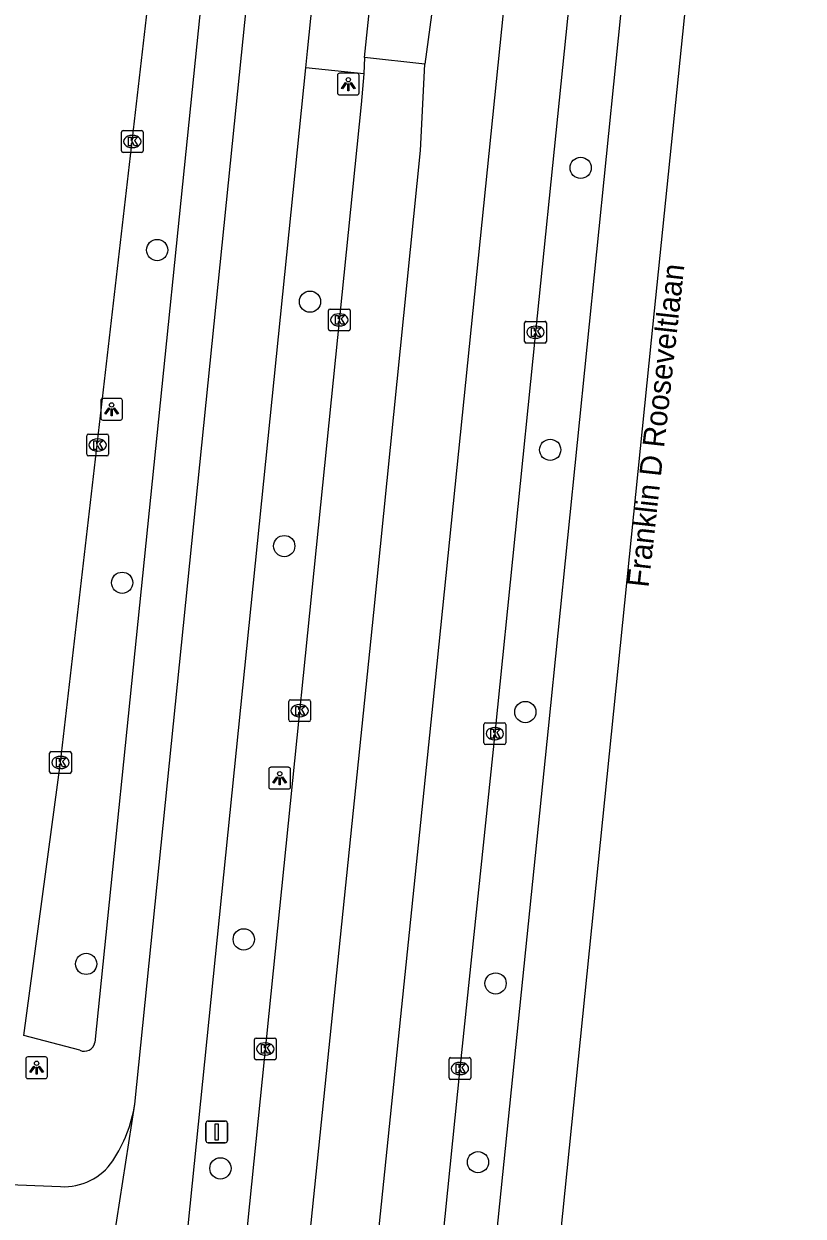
# Model space of a CAD drawing. Extents: x 160891 to 161384, y 386490 to 386907.
# Drawn here: x 161334.9 to 161370.7, y 386584.8 to 386639.6 of the extents above; entities that cross this region are included whole.
import ezdxf

# ---------------------------------------------------------------- set-up
doc = ezdxf.new("R2010")
doc.units = 0
for name, color, linetype in [('IMGEO_Boom', 7, 'Continuous'), ('IMGEO_Fietspad_gesloten', 7, 'Continuous'), ('IMGEO_Kolk', 7, 'Continuous'), ('IMGEO_Lichtpunt', 7, 'Continuous'), ('IMGEO_Openbare_ruimte_label', 7, 'Continuous'), ('IMGEO_Rijbaan_lokaal_gesloten', 7, 'Continuous'), ('IMGEO_Rijbaan_lokaal_open', 7, 'Continuous'), ('IMGEO_Verkeersbordpaal', 7, 'Continuous'), ('IMGEO_Voetpad_open', 7, 'Continuous')]:
    doc.layers.add(name, color=color, linetype=linetype)

msp = doc.modelspace()

# ---------------------------------------------------------------- linework, layer by layer
at = {"layer": 'IMGEO_Boom'}
for centre in [(161360.496, 386632.993), (161341.033, 386629.213), (161348.056, 386626.84), (161359.096, 386620.026), (161346.872, 386615.599), (161339.424, 386613.914), (161357.954, 386607.968), (161345.014, 386597.514), (161337.77, 386596.388), (161356.586, 386595.488), (161343.941, 386586.985), (161355.778, 386587.271)]:
    msp.add_circle(centre, 0.489, dxfattribs=at)
at = {"layer": 'IMGEO_Fietspad_gesloten'}
for points in [[(161340.003, 386589.938), (161344.586, 386635.023), (161348.773, 386676.071), (161350.75, 386695.389)], [(161336.452, 386525.646), (161336.548, 386526.649), (161337.443, 386534.03), (161338.136, 386542.124), (161339.032, 386551.069), (161341.141, 386571.584), (161342.161, 386581.483), (161347.861, 386637.589)], [(161338.485, 386580.159), (161340.003, 386589.938)], [(161314.741, 386587.177), (161314.693, 386587.03), (161314.685, 386587.006), (161336.596, 386586.148)]]:
    msp.add_lwpolyline(points, dxfattribs=at)
for centre, radius, start, end in [((161333.422, 386590.984), 6.663, 326.7857, 350.9683), ((161336.756, 386588.847), 2.704, 266.6, 325.9751)]:
    msp.add_arc(centre, radius, start, end, dxfattribs=at)
at = {"layer": 'IMGEO_Kolk'}
for p, q in [((161339.392, 386633.778), (161339.392, 386634.63)), ((161339.467, 386634.704), (161340.319, 386634.704)), ((161340.393, 386634.63), (161340.393, 386633.778)), ((161339.88, 386634.484), (161339.905, 386634.484)), ((161340.319, 386633.704), (161339.467, 386633.704)), ((161339.903, 386633.924), (161339.878, 386633.924)), ((161348.903, 386625.576), (161348.903, 386626.428)), ((161348.978, 386626.502), (161349.83, 386626.502)), ((161349.391, 386626.282), (161349.416, 386626.282)), ((161349.904, 386626.428), (161349.904, 386625.576)), ((161349.414, 386625.722), (161349.389, 386625.722)), ((161357.922, 386625.009), (161357.922, 386625.861)), ((161357.997, 386625.935), (161358.849, 386625.935)), ((161358.923, 386625.861), (161358.923, 386625.009)), ((161349.83, 386625.502), (161348.978, 386625.502)), ((161358.41, 386625.715), (161358.435, 386625.715)), ((161358.849, 386624.935), (161357.997, 386624.935)), ((161358.433, 386625.155), (161358.408, 386625.155)), ((161337.798, 386619.821), (161337.798, 386620.673)), ((161337.873, 386620.747), (161338.725, 386620.747)), ((161338.286, 386620.527), (161338.311, 386620.527)), ((161338.799, 386620.673), (161338.799, 386619.821)), ((161338.725, 386619.747), (161337.873, 386619.747)), ((161338.309, 386619.967), (161338.284, 386619.967)), ((161347.081, 386607.605), (161347.081, 386608.457)), ((161347.156, 386608.531), (161348.008, 386608.531)), ((161347.569, 386608.311), (161347.594, 386608.311)), ((161348.082, 386608.457), (161348.082, 386607.605)), ((161347.592, 386607.751), (161347.567, 386607.751)), ((161348.008, 386607.531), (161347.156, 386607.531)), ((161356.052, 386606.549), (161356.052, 386607.401)), ((161356.127, 386607.475), (161356.979, 386607.475)), ((161356.54, 386607.255), (161356.565, 386607.255)), ((161357.053, 386607.401), (161357.053, 386606.549)), ((161356.563, 386606.695), (161356.538, 386606.695)), ((161336.091, 386605.222), (161336.091, 386606.074)), ((161336.166, 386606.148), (161337.018, 386606.148)), ((161337.092, 386606.074), (161337.092, 386605.222)), ((161356.979, 386606.475), (161356.127, 386606.475)), ((161336.579, 386605.928), (161336.604, 386605.928)), ((161337.018, 386605.148), (161336.166, 386605.148)), ((161336.602, 386605.368), (161336.577, 386605.368)), ((161345.504, 386592.052), (161345.504, 386592.904)), ((161345.579, 386592.978), (161346.431, 386592.978)), ((161346.505, 386592.904), (161346.505, 386592.052)), ((161345.992, 386592.758), (161346.017, 386592.758)), ((161346.431, 386591.978), (161345.579, 386591.978)), ((161346.015, 386592.198), (161345.99, 386592.198)), ((161354.447, 386591.15), (161354.447, 386592.002)), ((161354.522, 386592.076), (161355.374, 386592.076)), ((161354.935, 386591.856), (161354.96, 386591.856)), ((161355.448, 386592.002), (161355.448, 386591.15)), ((161354.958, 386591.296), (161354.933, 386591.296)), ((161355.374, 386591.076), (161354.522, 386591.076))]:
    msp.add_line(p, q, dxfattribs=at)
for points in [[(161339.392, 386633.778), (161339.392, 386634.63)], [(161339.467, 386634.704), (161340.319, 386634.704)], [(161340.393, 386634.63), (161340.393, 386633.778)], [(161339.713, 386634.404), (161339.836, 386634.404), (161339.836, 386634.253), (161339.966, 386634.404), (161340.13, 386634.404), (161339.984, 386634.253), (161340.137, 386634.004), (161339.985, 386634.004), (161339.9, 386634.168), (161339.836, 386634.101), (161339.836, 386634.004), (161339.713, 386634.004), (161339.713, 386634.404)], [(161340.319, 386633.704), (161339.467, 386633.704)], [(161348.903, 386625.576), (161348.903, 386626.428)], [(161348.978, 386626.502), (161349.83, 386626.502)], [(161349.904, 386626.428), (161349.904, 386625.576)], [(161349.224, 386626.202), (161349.347, 386626.202), (161349.347, 386626.051), (161349.477, 386626.202), (161349.641, 386626.202), (161349.495, 386626.051), (161349.648, 386625.802), (161349.496, 386625.802), (161349.411, 386625.966), (161349.347, 386625.899), (161349.347, 386625.802), (161349.224, 386625.802), (161349.224, 386626.202)], [(161357.922, 386625.009), (161357.922, 386625.861)], [(161357.997, 386625.935), (161358.849, 386625.935)], [(161358.923, 386625.861), (161358.923, 386625.009)], [(161349.83, 386625.502), (161348.978, 386625.502)], [(161358.243, 386625.635), (161358.366, 386625.635), (161358.366, 386625.484), (161358.496, 386625.635), (161358.66, 386625.635), (161358.514, 386625.484), (161358.667, 386625.235), (161358.515, 386625.235), (161358.43, 386625.399), (161358.366, 386625.332), (161358.366, 386625.235), (161358.243, 386625.235), (161358.243, 386625.635)], [(161358.849, 386624.935), (161357.997, 386624.935)], [(161337.798, 386619.821), (161337.798, 386620.673)], [(161337.873, 386620.747), (161338.725, 386620.747)], [(161338.119, 386620.447), (161338.242, 386620.447), (161338.242, 386620.296), (161338.372, 386620.447), (161338.536, 386620.447), (161338.39, 386620.296), (161338.543, 386620.047), (161338.391, 386620.047), (161338.306, 386620.211), (161338.242, 386620.144), (161338.242, 386620.047), (161338.119, 386620.047), (161338.119, 386620.447)], [(161338.799, 386620.673), (161338.799, 386619.821)], [(161338.725, 386619.747), (161337.873, 386619.747)], [(161347.081, 386607.605), (161347.081, 386608.457)], [(161347.156, 386608.531), (161348.008, 386608.531)], [(161347.402, 386608.231), (161347.525, 386608.231), (161347.525, 386608.08), (161347.655, 386608.231), (161347.819, 386608.231), (161347.673, 386608.08), (161347.826, 386607.831), (161347.674, 386607.831), (161347.589, 386607.995), (161347.525, 386607.928), (161347.525, 386607.831), (161347.402, 386607.831), (161347.402, 386608.231)], [(161348.082, 386608.457), (161348.082, 386607.605)], [(161348.008, 386607.531), (161347.156, 386607.531)], [(161356.052, 386606.549), (161356.052, 386607.401)], [(161356.127, 386607.475), (161356.979, 386607.475)], [(161356.373, 386607.175), (161356.496, 386607.175), (161356.496, 386607.024), (161356.626, 386607.175), (161356.79, 386607.175), (161356.644, 386607.024), (161356.797, 386606.775), (161356.645, 386606.775), (161356.56, 386606.939), (161356.496, 386606.872), (161356.496, 386606.775), (161356.373, 386606.775), (161356.373, 386607.175)], [(161357.053, 386607.401), (161357.053, 386606.549)], [(161336.091, 386605.222), (161336.091, 386606.074)], [(161336.166, 386606.148), (161337.018, 386606.148)], [(161337.092, 386606.074), (161337.092, 386605.222)], [(161356.979, 386606.475), (161356.127, 386606.475)], [(161336.412, 386605.848), (161336.535, 386605.848), (161336.535, 386605.697), (161336.665, 386605.848), (161336.829, 386605.848), (161336.683, 386605.697), (161336.836, 386605.448), (161336.684, 386605.448), (161336.599, 386605.612), (161336.535, 386605.545), (161336.535, 386605.448), (161336.412, 386605.448), (161336.412, 386605.848)], [(161337.018, 386605.148), (161336.166, 386605.148)], [(161345.504, 386592.052), (161345.504, 386592.904)], [(161345.579, 386592.978), (161346.431, 386592.978)], [(161346.505, 386592.904), (161346.505, 386592.052)], [(161345.825, 386592.678), (161345.948, 386592.678), (161345.948, 386592.527), (161346.078, 386592.678), (161346.242, 386592.678), (161346.096, 386592.527), (161346.249, 386592.278), (161346.097, 386592.278), (161346.012, 386592.442), (161345.948, 386592.375), (161345.948, 386592.278), (161345.825, 386592.278), (161345.825, 386592.678)], [(161346.431, 386591.978), (161345.579, 386591.978)], [(161354.447, 386591.15), (161354.447, 386592.002)], [(161354.522, 386592.076), (161355.374, 386592.076)], [(161354.768, 386591.776), (161354.891, 386591.776), (161354.891, 386591.625), (161355.021, 386591.776), (161355.185, 386591.776), (161355.039, 386591.625), (161355.192, 386591.376), (161355.04, 386591.376), (161354.955, 386591.54), (161354.891, 386591.473), (161354.891, 386591.376), (161354.768, 386591.376), (161354.768, 386591.776)], [(161355.448, 386592.002), (161355.448, 386591.15)], [(161355.374, 386591.076), (161354.522, 386591.076)]]:
    msp.add_lwpolyline(points, dxfattribs=at)
for centre, start, end in [((161339.469, 386634.628), 91.552, 178.448), ((161339.469, 386634.628), 91.552, 178.448), ((161340.317, 386634.628), 1.552, 88.448), ((161340.317, 386634.628), 1.552, 88.448), ((161339.469, 386633.78), 181.552, 268.448), ((161339.469, 386633.78), 181.552, 268.448), ((161340.317, 386633.78), 271.552, 358.448), ((161340.317, 386633.78), 271.552, 358.448), ((161348.98, 386626.426), 91.552, 178.448), ((161348.98, 386626.426), 91.552, 178.448), ((161349.828, 386626.426), 1.552, 88.448), ((161349.828, 386626.426), 1.552, 88.448), ((161357.999, 386625.859), 91.552, 178.448), ((161357.999, 386625.859), 91.552, 178.448), ((161358.847, 386625.859), 1.552, 88.448), ((161358.847, 386625.859), 1.552, 88.448), ((161348.98, 386625.578), 181.552, 268.448), ((161348.98, 386625.578), 181.552, 268.448), ((161349.828, 386625.578), 271.552, 358.448), ((161349.828, 386625.578), 271.552, 358.448), ((161357.999, 386625.011), 181.552, 268.448), ((161357.999, 386625.011), 181.552, 268.448), ((161358.847, 386625.011), 271.552, 358.448), ((161358.847, 386625.011), 271.552, 358.448), ((161337.875, 386620.671), 91.552, 178.448), ((161337.875, 386620.671), 91.552, 178.448), ((161338.723, 386620.671), 1.552, 88.448), ((161338.723, 386620.671), 1.552, 88.448), ((161337.875, 386619.823), 181.552, 268.448), ((161337.875, 386619.823), 181.552, 268.448), ((161338.723, 386619.823), 271.552, 358.448), ((161338.723, 386619.823), 271.552, 358.448), ((161347.158, 386608.455), 91.552, 178.448), ((161347.158, 386608.455), 91.552, 178.448), ((161348.006, 386608.455), 1.552, 88.448), ((161348.006, 386608.455), 1.552, 88.448), ((161347.158, 386607.607), 181.552, 268.448), ((161347.158, 386607.607), 181.552, 268.448), ((161348.006, 386607.607), 271.552, 358.448), ((161348.006, 386607.607), 271.552, 358.448), ((161356.129, 386607.399), 91.552, 178.448), ((161356.129, 386607.399), 91.552, 178.448), ((161356.977, 386607.399), 1.552, 88.448), ((161356.977, 386607.399), 1.552, 88.448), ((161356.129, 386606.551), 181.552, 268.448), ((161356.129, 386606.551), 181.552, 268.448), ((161356.977, 386606.551), 271.552, 358.448), ((161356.977, 386606.551), 271.552, 358.448), ((161336.168, 386606.072), 91.552, 178.448), ((161336.168, 386606.072), 91.552, 178.448), ((161337.016, 386606.072), 1.552, 88.448), ((161337.016, 386606.072), 1.552, 88.448), ((161336.168, 386605.224), 181.552, 268.448), ((161336.168, 386605.224), 181.552, 268.448), ((161337.016, 386605.224), 271.552, 358.448), ((161337.016, 386605.224), 271.552, 358.448), ((161345.581, 386592.902), 91.552, 178.448), ((161345.581, 386592.902), 91.552, 178.448), ((161346.429, 386592.902), 1.552, 88.448), ((161346.429, 386592.902), 1.552, 88.448), ((161345.581, 386592.054), 181.552, 268.448), ((161345.581, 386592.054), 181.552, 268.448), ((161346.429, 386592.054), 271.552, 358.448), ((161346.429, 386592.054), 271.552, 358.448), ((161354.524, 386592), 91.552, 178.448), ((161354.524, 386592), 91.552, 178.448), ((161355.372, 386592), 1.552, 88.448), ((161355.372, 386592), 1.552, 88.448), ((161354.524, 386591.152), 181.552, 268.448), ((161354.524, 386591.152), 181.552, 268.448), ((161355.372, 386591.152), 271.552, 358.448), ((161355.372, 386591.152), 271.552, 358.448)]:
    msp.add_arc(centre, 0.0765, start, end, dxfattribs=at)
for centre, major_axis, ratio, start_param, end_param in [((161339.879, 386634.204), (-0.387, 0.002), 0.722429, 4.712389, 7.853982), ((161339.904, 386634.204), (-0.39, 0.002), 0.717154, 1.570796, 4.712389), ((161349.39, 386626.002), (-0.387, 0.002), 0.722429, 4.712389, 7.853982), ((161349.415, 386626.002), (-0.39, 0.002), 0.717154, 1.570796, 4.712389), ((161358.409, 386625.435), (-0.387, 0.002), 0.722429, 4.712389, 7.853982), ((161358.434, 386625.435), (-0.39, 0.002), 0.717154, 1.570796, 4.712389), ((161338.285, 386620.247), (-0.387, 0.002), 0.722429, 4.712389, 7.853982), ((161338.31, 386620.247), (-0.39, 0.002), 0.717154, 1.570796, 4.712389), ((161347.568, 386608.031), (-0.387, 0.002), 0.722429, 4.712389, 7.853982), ((161347.593, 386608.031), (-0.39, 0.002), 0.717154, 1.570796, 4.712389), ((161356.539, 386606.975), (-0.387, 0.002), 0.722429, 4.712389, 7.853982), ((161356.564, 386606.975), (-0.39, 0.002), 0.717154, 1.570796, 4.712389), ((161336.578, 386605.648), (-0.387, 0.002), 0.722429, 4.712389, 7.853982), ((161336.603, 386605.648), (-0.39, 0.002), 0.717154, 1.570796, 4.712389), ((161345.991, 386592.478), (-0.387, 0.002), 0.722429, 4.712389, 7.853982), ((161346.016, 386592.478), (-0.39, 0.002), 0.717154, 1.570796, 4.712389), ((161354.934, 386591.576), (-0.387, 0.002), 0.722429, 4.712389, 7.853982), ((161354.959, 386591.576), (-0.39, 0.002), 0.717154, 1.570796, 4.712389)]:
    msp.add_ellipse(centre, major_axis=major_axis, ratio=ratio, start_param=start_param, end_param=end_param, dxfattribs=at)
at = {"layer": 'IMGEO_Lichtpunt'}
for p, q in [((161349.32, 386637.248), (161349.32, 386636.441)), ((161349.32, 386637.248), (161349.32, 386636.441)), ((161350.222, 386637.343), (161349.414, 386637.343)), ((161350.222, 386637.343), (161349.414, 386637.343)), ((161350.316, 386636.441), (161350.316, 386637.248)), ((161350.316, 386636.441), (161350.316, 386637.248)), ((161349.414, 386636.347), (161350.222, 386636.347)), ((161349.414, 386636.347), (161350.222, 386636.347)), ((161338.44, 386622.295), (161338.44, 386621.488)), ((161338.44, 386622.295), (161338.44, 386621.488)), ((161339.342, 386622.39), (161338.534, 386622.39)), ((161339.342, 386622.39), (161338.534, 386622.39)), ((161339.436, 386621.488), (161339.436, 386622.295)), ((161339.436, 386621.488), (161339.436, 386622.295)), ((161338.534, 386621.394), (161339.342, 386621.394)), ((161338.534, 386621.394), (161339.342, 386621.394)), ((161346.165, 386605.332), (161346.165, 386604.525)), ((161346.165, 386605.332), (161346.165, 386604.525)), ((161347.067, 386605.427), (161346.259, 386605.427)), ((161347.067, 386605.427), (161346.259, 386605.427)), ((161347.161, 386604.525), (161347.161, 386605.332)), ((161347.161, 386604.525), (161347.161, 386605.332)), ((161346.259, 386604.431), (161347.067, 386604.431)), ((161346.259, 386604.431), (161347.067, 386604.431)), ((161334.993, 386592.019), (161334.993, 386591.212)), ((161334.993, 386592.019), (161334.993, 386591.212)), ((161335.895, 386592.114), (161335.087, 386592.114)), ((161335.895, 386592.114), (161335.087, 386592.114)), ((161335.989, 386591.212), (161335.989, 386592.019)), ((161335.989, 386591.212), (161335.989, 386592.019)), ((161335.087, 386591.118), (161335.895, 386591.118)), ((161335.087, 386591.118), (161335.895, 386591.118))]:
    msp.add_line(p, q, dxfattribs=at)
for points in [[(161349.694, 386636.912), (161349.733, 386636.884), (161349.545, 386636.622), (161349.507, 386636.649), (161349.694, 386636.912)], [(161349.796, 386636.864), (161349.843, 386636.864), (161349.843, 386636.542), (161349.796, 386636.542), (161349.796, 386636.864)], [(161349.906, 386636.884), (161349.944, 386636.911), (161350.131, 386636.649), (161350.092, 386636.621), (161349.906, 386636.884)], [(161338.814, 386621.959), (161338.853, 386621.931), (161338.665, 386621.669), (161338.627, 386621.696), (161338.814, 386621.959)], [(161338.916, 386621.911), (161338.963, 386621.911), (161338.963, 386621.589), (161338.916, 386621.589), (161338.916, 386621.911)], [(161339.026, 386621.931), (161339.064, 386621.958), (161339.251, 386621.696), (161339.212, 386621.668), (161339.026, 386621.931)], [(161346.539, 386604.996), (161346.578, 386604.968), (161346.39, 386604.706), (161346.352, 386604.733), (161346.539, 386604.996)], [(161346.641, 386604.948), (161346.688, 386604.948), (161346.688, 386604.626), (161346.641, 386604.626), (161346.641, 386604.948)], [(161346.751, 386604.968), (161346.789, 386604.995), (161346.976, 386604.733), (161346.937, 386604.705), (161346.751, 386604.968)], [(161335.367, 386591.683), (161335.406, 386591.655), (161335.218, 386591.393), (161335.18, 386591.42), (161335.367, 386591.683)], [(161335.469, 386591.635), (161335.516, 386591.635), (161335.516, 386591.313), (161335.469, 386591.313), (161335.469, 386591.635)], [(161335.579, 386591.655), (161335.617, 386591.682), (161335.804, 386591.42), (161335.765, 386591.392), (161335.579, 386591.655)]]:
    msp.add_lwpolyline(points, dxfattribs=at)
for centre in [(161349.819, 386637.046), (161338.939, 386622.093), (161346.664, 386605.13), (161335.492, 386591.817)]:
    msp.add_circle(centre, 0.0994, dxfattribs=at)
for centre, start, end in [((161349.414, 386637.248), 90, 180), ((161349.414, 386637.248), 90, 180), ((161350.222, 386637.248), 0, 90), ((161350.222, 386637.248), 0, 90), ((161349.414, 386636.441), 180, 270), ((161349.414, 386636.441), 180, 270), ((161350.222, 386636.441), 270, 0), ((161350.222, 386636.441), 270, 360), ((161338.534, 386622.295), 90, 180), ((161338.534, 386622.295), 90, 180), ((161339.342, 386622.295), 0, 90), ((161339.342, 386622.295), 0, 90), ((161338.534, 386621.488), 180, 270), ((161338.534, 386621.488), 180, 270), ((161339.342, 386621.488), 270, 0), ((161339.342, 386621.488), 270, 360), ((161346.259, 386605.332), 90, 180), ((161346.259, 386605.332), 90, 180), ((161347.067, 386605.332), 0, 90), ((161347.067, 386605.332), 0, 90), ((161346.259, 386604.525), 180, 270), ((161346.259, 386604.525), 180, 270), ((161347.067, 386604.525), 270, 0), ((161347.067, 386604.525), 270, 360), ((161335.087, 386592.019), 90, 180), ((161335.087, 386592.019), 90, 180), ((161335.895, 386592.019), 0, 90), ((161335.895, 386592.019), 0, 90), ((161335.087, 386591.212), 180, 270), ((161335.087, 386591.212), 180, 270), ((161335.895, 386591.212), 270, 0), ((161335.895, 386591.212), 270, 360)]:
    msp.add_arc(centre, 0.0946, start, end, dxfattribs=at)
at = {"layer": 'IMGEO_Rijbaan_lokaal_gesloten'}
for points in [[(161350.321, 386526.461), (161352.302, 386541.627), (161357.382, 386591.194), (161359.018, 386607.209), (161363.024, 386646.681), (161367.022, 386685.397), (161367.598, 386691.178), (161367.683, 386693.586)], [(161370.722, 386693.301), (161368.799, 386674.486), (161363.732, 386625.065), (161353.345, 386522.715)], [(161344.957, 386522.245), (161345.695, 386529.16), (161349.223, 386564.812), (161353.824, 386609.435), (161360.75, 386677.447), (161361.036, 386681.278)], [(161364.125, 386681.052), (161362.491, 386665.206), (161360.59, 386646.794), (161358.423, 386625.435), (161356.553, 386606.975), (161354.948, 386591.576), (161352.778, 386570.251), (161350.673, 386549.854), (161349.854, 386541.879), (161348.259, 386526.488)], [(161350.569, 386638.061), (161352.745, 386658.865), (161353.211, 386660.371), (161354.412, 386665.035), (161357.015, 386675.238)], [(161357.015, 386675.238), (161357.193, 386675.204), (161353.638, 386640.03), (161353.333, 386637.758)], [(161350.569, 386638.061), (161350.537, 386637.31)], [(161353.333, 386637.758), (161350.569, 386638.061)], [(161350.537, 386637.31), (161350.408, 386635.904), (161344.884, 386581.428), (161343.814, 386571.25), (161341.755, 386550.887), (161339.538, 386529.553), (161339.176, 386526.026), (161339.147, 386525.679)], [(161341.732, 386522.048), (161343.29, 386537.458), (161350.996, 386612.554), (161353.14, 386633.788), (161353.333, 386637.758)]]:
    msp.add_lwpolyline(points, dxfattribs=at)
at = {"layer": 'IMGEO_Rijbaan_lokaal_open'}
for points in [[(161347.861, 386637.589), (161347.94, 386638.364), (161351.757, 386675.763)], [(161334.906, 386593.09), (161336.592, 386605.648), (161343.202, 386663.059)], [(161350.537, 386637.31), (161347.861, 386637.589)]]:
    msp.add_lwpolyline(points, dxfattribs=at)
at = {"layer": 'IMGEO_Verkeersbordpaal'}
for p, q in [((161343.273, 386588.263), (161343.273, 386589.063)), ((161343.273, 386589.063), (161343.273, 386588.263)), ((161343.373, 386589.163), (161344.163, 386589.163)), ((161344.163, 386589.163), (161343.373, 386589.163)), ((161344.263, 386589.063), (161344.263, 386588.263)), ((161344.263, 386588.263), (161344.263, 386589.063)), ((161344.163, 386588.163), (161343.373, 386588.163)), ((161343.373, 386588.163), (161344.163, 386588.163))]:
    msp.add_line(p, q, dxfattribs=at)
msp.add_lwpolyline([(161343.693, 386589.038), (161343.843, 386589.038), (161343.843, 386588.288), (161343.693, 386588.288), (161343.693, 386589.038)], dxfattribs=at)
for centre, start, end in [((161343.373, 386589.063), 90, 180), ((161343.373, 386589.063), 90, 180), ((161344.163, 386589.063), 0, 90), ((161344.163, 386589.063), 360, 90), ((161343.373, 386588.263), 180, 270), ((161343.373, 386588.263), 180, 270), ((161344.163, 386588.263), 270, 0), ((161344.163, 386588.263), 270, 0)]:
    msp.add_arc(centre, 0.1, start, end, dxfattribs=at)
at = {"layer": 'IMGEO_Voetpad_open'}
for points in [[(161348.346, 386692.534), (161346.713, 386676.405), (161342.863, 386638.693), (161338.172, 386592.768)], [(161337.474, 386592.417), (161334.906, 386593.09)]]:
    msp.add_lwpolyline(points, dxfattribs=at)
msp.add_arc((161337.686, 386592.864), 0.495, 244.5938, 348.7987, dxfattribs=at)

# ---------------------------------------------------------------- texts
at = {"layer": 'IMGEO_Openbare_ruimte_label'}
msp.add_text('Franklin D Rooseveltlaan', height=1, rotation=83.6282, dxfattribs=at).set_placement((161363.611, 386613.672))

doc.saveas('drawing.dxf')
